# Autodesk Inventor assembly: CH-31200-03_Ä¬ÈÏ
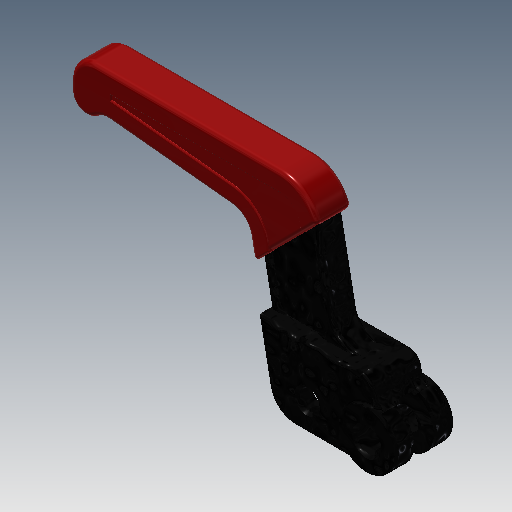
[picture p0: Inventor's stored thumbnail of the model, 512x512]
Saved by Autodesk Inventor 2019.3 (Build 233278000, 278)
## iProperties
Created: 2010-06
Part Number: CH-31200-03_Ä¬ÈÏ
Material: Ogólny
Document SubType Name: Assembly
Designer: CADENGINEERING4
Author: CADENGINEERING4
Revision Number: ÈÎºÎ
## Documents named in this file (3)
- D:\Vault_2016\Projekty\STRONA\Push-pull clamp\CH-31200\CH-31200-03_Ä¬ÈÏ.iam
- D:\Vault_2016\Projekty\STRONA\Push-pull clamp\CH-31200\CH-31200-03-1_Ä¬ÈÏ.ipt
- D:\Vault_2016\Projekty\STRONA\Push-pull clamp\CH-31200\CH-31200-03_Ä¬ÈÏ.ipt
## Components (2 placed, 2 different names)
1. CH-31200-03-1_Ä¬ÈÏ_11
2. CH-31200-03_Ä¬ÈÏ_12
